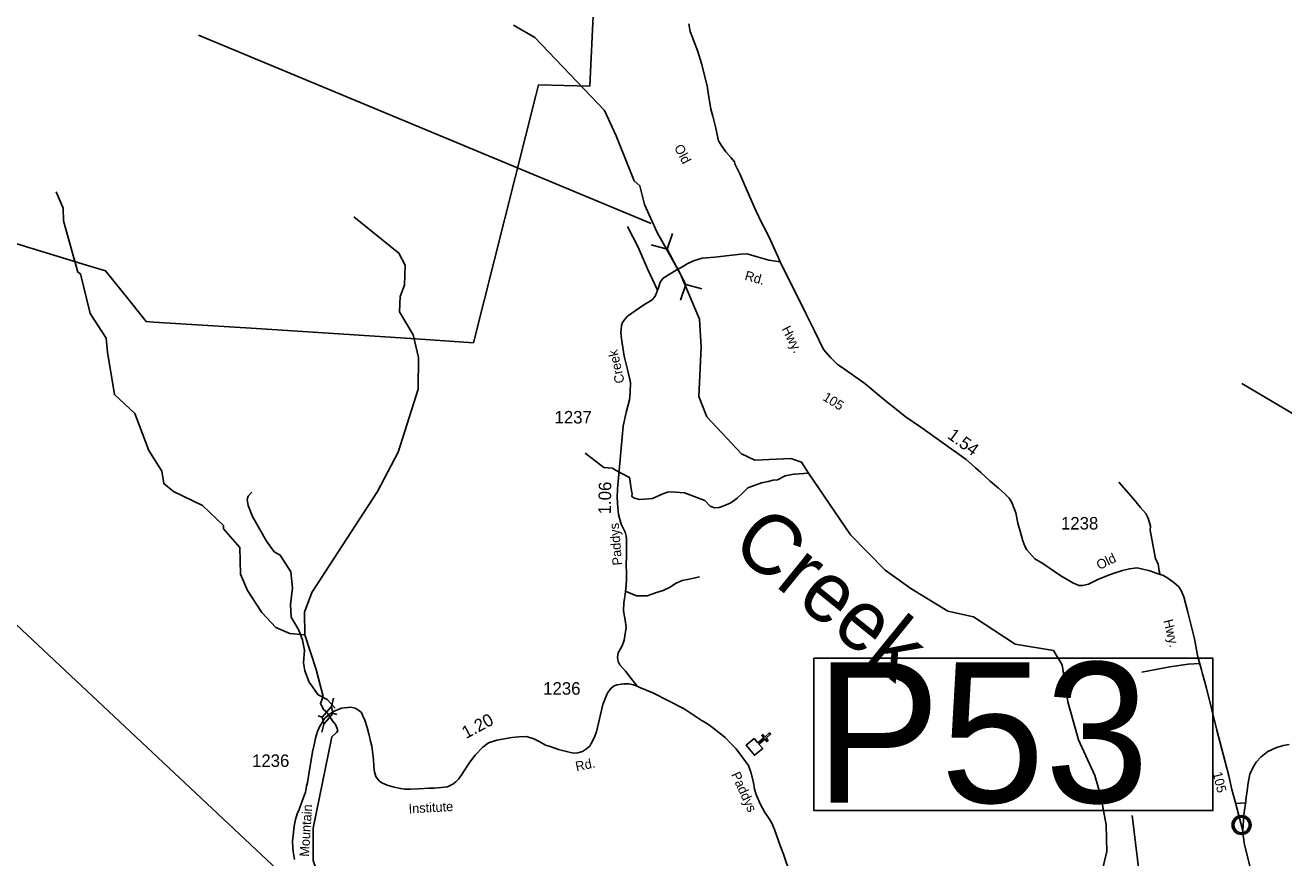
# Model space of a CAD drawing. Extents: x 1113032 to 1302912, y 664689 to 832535.
# Drawn here: x 1126972 to 1139525, y 747949 to 756257 of the extents above; entities that cross this region are included whole.
import ezdxf

# ---------------------------------------------------------------- set-up
doc = ezdxf.new("R2010")
doc.units = 0
for name, color, linetype in [('Exist Boundary Land Use Forest National US Forest Service', 7, 'Continuous'), ('Exist Boundary Political CountyLine', 7, 'Continuous'), ('Exist Civil Demographics Community CELL', 7, 'Continuous'), ('Exist Cultural Church CELL', 7, 'Continuous'), ('Exist Hydrographic Creek Single Shore', 7, 'Continuous'), ('Exist Hydrographic Creek Single Shore Label', 7, 'Continuous'), ('Exist Road Non-System Type 51', 7, 'Continuous'), ('Exist Road Primary NC Attributed', 7, 'Continuous'), ('Exist Road Primary NC Structure Pipe Attributed CELL', 7, 'Continuous'), ('Exist Road Primary NC Structure Pipe Number Label', 7, 'Continuous'), ('Exist Road Secondary Mileage Hundredths English Label', 7, 'Continuous'), ('Exist Road Secondary Structure Standard Bridge CELL', 7, 'Continuous'), ('Exist Road Secondary Type 41 Attributed', 7, 'Continuous'), ('Exist Road Secondary Type 51 Attributed', 7, 'Continuous'), ('Exist Road Secondary Type 51 Label', 7, 'Continuous'), ('Exist Road Secondary Type 51 Number Label', 7, 'Continuous')]:
    doc.layers.add(name, color=color, linetype=linetype)

msp = doc.modelspace()

# ---------------------------------------------------------------- linework, layer by layer
at = {"layer": 'Exist Boundary Land Use Forest National US Forest Service'}
msp.add_lwpolyline([(1132670, 757055), (1132603, 755652), (1132603, 755648), (1132092, 755661), (1132066, 755557), (1131443, 753089), (1130867, 753127), (1129279, 753229), (1128257, 753294), (1128180, 753299), (1128139, 753350), (1128008, 753513), (1127774, 753805), (1127583, 753864), (1126104, 754314)], dxfattribs=at)
at = {"layer": 'Exist Boundary Political CountyLine'}
msp.add_lwpolyline([(1114483, 761941), (1121830, 755021), (1129762, 747575), (1131999, 745470), (1132534, 744970), (1136601, 740851), (1137713, 739712), (1140850, 736413), (1141222, 736061), (1141222, 736061), (1142712, 734629), (1146817, 730670), (1148405, 729150)], dxfattribs=at)
at = {"layer": 'Exist Civil Demographics Community CELL'}
msp.add_lwpolyline([(1139027, 748290), (1139028, 748295), (1139029, 748302), (1139032, 748309), (1139035, 748315), (1139039, 748320), (1139042, 748325), (1139046, 748330), (1139051, 748334), (1139057, 748339), (1139062, 748343), (1139067, 748346), (1139072, 748348), (1139077, 748350), (1139083, 748352), (1139087, 748353), (1139092, 748354), (1139096, 748355), (1139103, 748355), (1139107, 748355), (1139113, 748355), (1139118, 748354), (1139123, 748353), (1139128, 748351), (1139133, 748350), (1139139, 748347), (1139146, 748343), (1139151, 748340), (1139156, 748336), (1139159, 748332), (1139163, 748328), (1139167, 748323), (1139170, 748319), (1139173, 748314), (1139176, 748309), (1139178, 748304), (1139179, 748299), (1139181, 748294), (1139182, 748288), (1139182, 748283), (1139183, 748277), (1139183, 748271), (1139182, 748266), (1139181, 748260), (1139179, 748254), (1139177, 748248), (1139175, 748243), (1139172, 748237), (1139169, 748232), (1139165, 748227), (1139161, 748222), (1139156, 748217), (1139151, 748213), (1139146, 748210), (1139141, 748207), (1139135, 748204), (1139127, 748201), (1139122, 748200), (1139115, 748199), (1139110, 748198), (1139106, 748198), (1139100, 748198), (1139096, 748198), (1139090, 748199), (1139085, 748200), (1139080, 748202), (1139075, 748204), (1139070, 748206), (1139066, 748208), (1139060, 748212), (1139054, 748216), (1139049, 748221), (1139045, 748226), (1139041, 748230), (1139038, 748234), (1139034, 748241), (1139033, 748244), (1139031, 748248), (1139028, 748257), (1139027, 748264), (1139026, 748269), (1139026, 748275), (1139026, 748280), (1139026, 748286)], close=True, dxfattribs=at)
for radius in [94.3, 76.7]:
    msp.add_circle((1139104, 748277), radius, dxfattribs=at)
at = {"layer": 'Exist Cultural Church CELL'}
msp.add_lwpolyline([(1134243, 749140), (1134280, 749097), (1134338, 749146), (1134318, 749171), (1134330, 749181), (1134351, 749156), (1134397, 749195), (1134407, 749183), (1134361, 749144), (1134381, 749120), (1134369, 749109), (1134349, 749134), (1134290, 749085), (1134328, 749041), (1134246, 748972), (1134162, 749072)], close=True, dxfattribs=at)
at = {"layer": 'Exist Hydrographic Creek Single Shore'}
for points in [[(1134785, 751788), (1134715, 751897), (1134608, 751932), (1134249, 751916), (1134118, 751981), (1133770, 752349), (1133692, 752551), (1133715, 753043), (1133699, 753325), (1133505, 753779), (1133274, 754190), (1133148, 754469), (1133103, 754653), (1133047, 754704), (1132868, 755154), (1132750, 755405), (1132055, 756135), (1131841, 756257)], [(1129761, 750174), (1129612, 750187), (1129472, 750249), (1129334, 750396), (1129191, 750616), (1129120, 750778), (1129112, 751044), (1128950, 751231), (1128951, 751264), (1128740, 751465), (1128452, 751605), (1128354, 751683), (1128334, 751808), (1128205, 752014), (1128066, 752384), (1127863, 752572), (1127793, 752994), (1127780, 753135), (1127620, 753381), (1127524, 753777), (1127499, 753794), (1127356, 754305), (1127351, 754430), (1127281, 754593)], [(1129761, 750174), (1129759, 750401), (1129832, 750596), (1130487, 751604), (1130691, 751997), (1130892, 752626), (1130894, 752941), (1130842, 753169), (1130707, 753398), (1130712, 753549), (1130757, 753663), (1130762, 753863), (1130700, 753983), (1130251, 754346)], [(1143517, 747815), (1143273, 748023), (1142876, 748126), (1142671, 748248), (1142566, 748346), (1142478, 748462), (1142439, 748591), (1142461, 748748), (1142610, 749293), (1142673, 750008), (1142595, 750479), (1142531, 750572), (1142441, 750626), (1142317, 750635), (1142261, 750738), (1142256, 750856), (1142195, 751025), (1142081, 751136), (1141458, 751496), (1140658, 751778), (1140034, 752132), (1139108, 752682)], [(1132556, 751987), (1132713, 751867), (1132744, 751844), (1132788, 751840), (1132831, 751836), (1132867, 751815), (1132922, 751784), (1132999, 751744), (1133002, 751728), (1133009, 751676), (1133019, 751612), (1133025, 751583), (1133023, 751557), (1133027, 751551), (1133049, 751539), (1133098, 751525), (1133193, 751530), (1133230, 751534), (1133332, 751580), (1133379, 751596), (1133413, 751601), (1133549, 751591), (1133751, 751513), (1133805, 751457), (1133846, 751442), (1133893, 751446), (1133939, 751461), (1134010, 751492), (1134072, 751539), (1134130, 751590), (1134180, 751642), (1134317, 751692), (1134383, 751705), (1134433, 751717), (1134474, 751720), (1134553, 751761), (1134618, 751773), (1134644, 751778), (1134785, 751788)], [(1138196, 746280), (1138202, 746562), (1138157, 746747), (1138062, 746903), (1137711, 747445), (1137671, 747521), (1137685, 747695), (1137761, 748012), (1137752, 748278), (1137702, 748564), (1137642, 748772), (1137477, 749127), (1137372, 749507), (1137316, 749875), (1137228, 750018), (1136847, 750082), (1136429, 750353), (1136173, 750410), (1135804, 750637), (1135551, 750820), (1135203, 751171), (1134785, 751788)], [(1129988, 747363), (1129987, 747389), (1129929, 747683), (1129845, 747921), (1129846, 748246), (1130030, 749155), (1130076, 749199), (1130089, 749217), (1130083, 749238), (1130066, 749279), (1130036, 749315), (1129978, 749406), (1129951, 749426), (1129928, 749470), (1129917, 749490), (1129943, 749560), (1129876, 749827), (1129761, 750174)]]:
    msp.add_lwpolyline(points, dxfattribs=at)
at = {"layer": 'Exist Road Non-System Type 51'}
msp.add_line((1139143, 748499), (1139044, 748492), dxfattribs=at)
for points in [[(1133280, 753612), (1133179, 753825), (1133087, 754041), (1132979, 754249)], [(1138291, 750777), (1138281, 750808), (1138271, 750882), (1138246, 750931), (1138191, 751217), (1138196, 751259), (1138172, 751337), (1138148, 751386), (1138095, 751444), (1138022, 751536), (1137881, 751696)], [(1129239, 751355), (1129195, 751465), (1129187, 751525), (1129197, 751557), (1129233, 751596)], [(1130064, 749441), (1129984, 749529), (1129896, 749575), (1129804, 749703), (1129761, 749816), (1129748, 749896), (1129758, 750021), (1129737, 750120), (1129702, 750221), (1129626, 750352), (1129618, 750478), (1129639, 750643), (1129622, 750803), (1129516, 750970), (1129454, 751003), (1129378, 751110), (1129239, 751355)], [(1132966, 750606), (1133069, 750562), (1133177, 750562), (1133269, 750597), (1133335, 750617), (1133404, 750649), (1133459, 750688), (1133525, 750716), (1133596, 750730), (1133699, 750752)], [(1138688, 749888), (1138572, 749880), (1138389, 749856), (1138109, 749802)]]:
    msp.add_lwpolyline(points, dxfattribs=at)
at = {"layer": 'Exist Road Primary NC Attributed'}
for points in [[(1139117, 748220), (1139128, 748377), (1139145, 748516), (1139149, 748559), (1139155, 748590), (1139171, 748698), (1139188, 748784), (1139220, 748854), (1139251, 748903), (1139298, 748957), (1139366, 749009), (1139445, 749047), (1139520, 749070), (1139580, 749079)], [(1139286, 747338), (1139289, 747383), (1139281, 747436), (1139276, 747477), (1139265, 747522), (1139241, 747641), (1139226, 747694), (1139214, 747764), (1139129, 748091), (1139126, 748132), (1139117, 748189), (1139117, 748220)]]:
    msp.add_lwpolyline(points, dxfattribs=at)
at = {"layer": 'Exist Road Primary NC Structure Pipe Attributed CELL'}
for p, q in [((1133428, 754179), (1133375, 754021)), ((1133214, 754066), (1133375, 754021)), ((1133560, 753670), (1133375, 754021)), ((1133507, 753513), (1133560, 753670)), ((1133721, 753626), (1133560, 753670))]:
    msp.add_line(p, q, dxfattribs=at)
at = {"layer": 'Exist Road Primary NC Structure Pipe Number Label'}
for p, q in [((1133215, 754277), (1128701, 756156)), ((1138210, 746773), (1138013, 748372))]:
    msp.add_line(p, q, dxfattribs=at)
msp.add_lwpolyline([(1134838, 749941), (1138819, 749941), (1138819, 748421), (1134838, 748421)], close=True, dxfattribs=at)
at = {"layer": 'Exist Road Secondary Structure Standard Bridge CELL'}
for p, q in [((1130027, 749459), (1130046, 749541)), ((1129894, 749366), (1129934, 749353)), ((1130041, 749392), (1130082, 749379)), ((1129930, 749202), (1129950, 749284))]:
    msp.add_line(p, q, dxfattribs=at)
msp.add_lwpolyline([(1129934, 749353), (1130027, 749459), (1130042, 749390), (1129950, 749284)], close=True, dxfattribs=at)
at = {"layer": 'Exist Road Secondary Type 41 Attributed'}
for points in [[(1133591, 756272), (1133603, 756195), (1133639, 756106), (1133681, 755993), (1133716, 755876), (1133774, 755653), (1133788, 755561)], [(1132965, 750667), (1132968, 750729), (1132968, 750791), (1132967, 750877), (1132969, 750953), (1132970, 751077), (1132971, 751135), (1132965, 751157), (1132955, 751197), (1132918, 751278), (1132889, 751375), (1132882, 751441), (1132878, 751544), (1132879, 751632), (1132936, 752257), (1132966, 752393), (1132999, 752520), (1133006, 752595), (1133010, 752691), (1132987, 752795), (1132945, 752955), (1132920, 753126), (1132913, 753192), (1132915, 753220), (1132919, 753261), (1132931, 753289), (1132945, 753314), (1132981, 753355), (1133098, 753436), (1133154, 753472), (1133204, 753502), (1133230, 753521), (1133254, 753553), (1133273, 753594), (1133280, 753614), (1133289, 753638), (1133305, 753694), (1133336, 753734), (1133404, 753777), (1133464, 753814), (1133520, 753843), (1133576, 753876), (1133637, 753905), (1133681, 753920), (1133725, 753932), (1133849, 753941), (1133908, 753949), (1134109, 753971), (1134169, 753975), (1134207, 753965), (1134272, 753946), (1134319, 753933), (1134390, 753913), (1134501, 753897)]]:
    msp.add_lwpolyline(points, dxfattribs=at)
at = {"layer": 'Exist Road Secondary Type 51 Attributed'}
for points in [[(1133788, 755561), (1133810, 755419), (1133829, 755348), (1133862, 755229), (1133870, 755180), (1133887, 755102), (1133919, 755051), (1133959, 754993), (1134010, 754938), (1134046, 754895), (1134055, 754868), (1134100, 754774), (1134151, 754659), (1134255, 754413), (1134319, 754280), (1134368, 754190), (1134406, 754111), (1134481, 753941), (1134501, 753897)], [(1134501, 753897), (1134764, 753367), (1134844, 753207), (1134936, 753020), (1135006, 752939), (1135072, 752876), (1135143, 752824), (1135348, 752681), (1135469, 752578), (1135571, 752497), (1135645, 752436), (1135749, 752352), (1135905, 752246), (1136139, 752081), (1136356, 751925), (1136449, 751840), (1136505, 751795), (1136595, 751708), (1136680, 751639), (1136739, 751586), (1136768, 751556), (1136785, 751537), (1136813, 751495), (1136835, 751434), (1136852, 751392), (1136873, 751289), (1136895, 751209), (1136922, 751112), (1136944, 751060), (1136963, 751021), (1137043, 750934), (1137121, 750887), (1137301, 750762), (1137421, 750693), (1137480, 750667), (1137521, 750668), (1137577, 750681), (1137672, 750727), (1137759, 750763), (1137834, 750789), (1137916, 750817), (1137986, 750834), (1138062, 750844), (1138190, 750812), (1138263, 750786), (1138301, 750774), (1138318, 750769), (1138370, 750740), (1138427, 750698), (1138479, 750652), (1138502, 750617), (1138529, 750552), (1138568, 750401), (1138634, 750133), (1138653, 750024), (1138669, 749954), (1138692, 749873), (1138703, 749825), (1138714, 749784), (1138754, 749641), (1138858, 749224), (1138939, 748907), (1138977, 748769), (1139008, 748631), (1139039, 748512), (1139117, 748220)], [(1133075, 749662), (1132994, 749770), (1132959, 749813), (1132904, 749874), (1132888, 749908), (1132880, 749948), (1132887, 749995), (1132926, 750063), (1132946, 750120), (1132954, 750165), (1132967, 750247), (1132960, 750301), (1132941, 750414), (1132944, 750495), (1132949, 750537), (1132955, 750578), (1132965, 750667)], [(1129657, 747933), (1129644, 748013), (1129641, 748050), (1129640, 748115), (1129644, 748173), (1129655, 748266), (1129669, 748332), (1129684, 748388), (1129704, 748431), (1129716, 748463), (1129734, 748516), (1129748, 748551), (1129767, 748605), (1129779, 748663), (1129788, 748701), (1129805, 748805), (1129839, 749006), (1129853, 749078), (1129867, 749144), (1129889, 749211), (1129908, 749256), (1129933, 749298), (1129958, 749338), (1130006, 749383), (1130046, 749408), (1130128, 749441), (1130220, 749452), (1130263, 749444), (1130298, 749423), (1130317, 749407), (1130325, 749399), (1130337, 749374), (1130360, 749323), (1130382, 749251), (1130401, 749185), (1130418, 749114), (1130431, 749063), (1130436, 749015), (1130447, 748928), (1130448, 748868), (1130452, 748831), (1130456, 748807), (1130463, 748783), (1130470, 748762), (1130487, 748739), (1130505, 748715), (1130531, 748697), (1130581, 748675), (1130651, 748653), (1130717, 748641), (1130759, 748636), (1130815, 748635), (1130896, 748638), (1130998, 748645), (1131052, 748645), (1131120, 748651), (1131184, 748659), (1131211, 748672), (1131239, 748684), (1131266, 748706), (1131293, 748735), (1131326, 748782), (1131374, 748855), (1131408, 748903), (1131460, 748973), (1131536, 749052), (1131593, 749097), (1131677, 749124), (1131827, 749150), (1131897, 749157), (1131971, 749159), (1132045, 749135), (1132104, 749106), (1132163, 749072), (1132207, 749059), (1132292, 749031), (1132370, 749010), (1132411, 749000), (1132444, 748995), (1132485, 748997), (1132532, 749011), (1132572, 749036), (1132603, 749065), (1132617, 749089), (1132648, 749147), (1132671, 749208), (1132732, 749479), (1132773, 749580), (1132783, 749600), (1132818, 749641), (1132848, 749664), (1132876, 749675), (1132919, 749683), (1132944, 749686), (1132993, 749685), (1133041, 749674), (1133075, 749662)], [(1133075, 749662), (1133103, 749649), (1133232, 749597), (1133546, 749435), (1133724, 749317), (1133767, 749293), (1133826, 749251), (1133953, 749150), (1134010, 749090), (1134065, 749036), (1134188, 748871), (1134209, 748804), (1134236, 748702), (1134247, 748636), (1134264, 748581), (1134303, 748487), (1134349, 748403), (1134382, 748354), (1134419, 748295), (1134445, 748232), (1134505, 748061), (1134534, 747986), (1134603, 747788)]]:
    msp.add_lwpolyline(points, dxfattribs=at)

# ---------------------------------------------------------------- texts
at = {"layer": 'Exist Hydrographic Creek Single Shore Label'}
msp.add_text('Creek', height=600, rotation=320.9488, dxfattribs=at).set_placement((1133991, 751033))
at = {"layer": 'Exist Road Primary NC Structure Pipe Number Label'}
msp.add_text('P53', height=1400, dxfattribs=at).set_placement((1134851, 748500))
at = {"layer": 'Exist Road Secondary Mileage Hundredths English Label'}
for s, rotation, p in [('1.54', 324.2751, (1136161, 752143)), ('1.06', 89.1189, (1132813, 751376)), ('1.20', 28.0227, (1131369, 749134))]:
    msp.add_text(s, height=125, rotation=rotation, dxfattribs=at).set_placement(p)
at = {"layer": 'Exist Road Secondary Type 51 Label'}
for s, rotation, p in [('Old', 297.6191, (1133442, 755038)), ('Rd.', 344.6646, (1134142, 753717)), ('Hwy.', 296.8236, (1134515, 753227)), ('Creek', 102.7454, (1132952, 752695)), ('105', 328.0437, (1134919, 752521)), ('Paddys', 94.7109, (1132927, 750871)), ('Old', 26.2835, (1137686, 750820)), ('Hwy.', 283.8805, (1138323, 750316)), ('Rd.', 11.3461, (1132471, 748813)), ('Paddys', 294.4201, (1134011, 748781)), ('105', 283.8129, (1138814, 748796)), ('Mountain', 86.3784, (1129802, 747958)), ('Institute', 3.182, (1130799, 748392))]:
    msp.add_text(s, height=95, rotation=rotation, dxfattribs=at).set_placement(p)
at = {"layer": 'Exist Road Secondary Type 51 Number Label'}
for s, p in [('1237', (1132252, 752283)), ('1238', (1137303, 751225)), ('1236', (1132139, 749577)), ('1236', (1129235, 748856))]:
    msp.add_text(s, height=125, dxfattribs=at).set_placement(p)

doc.saveas('drawing.dxf')
